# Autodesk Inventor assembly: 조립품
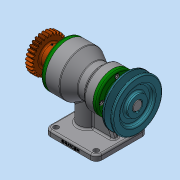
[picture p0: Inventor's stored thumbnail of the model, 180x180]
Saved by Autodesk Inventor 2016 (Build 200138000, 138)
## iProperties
Created: 2019-01
Part Number: 조립품
Material: 일반
Document SubType Name: Assembly
Designer: Administrator
Author: Administrator
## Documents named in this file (15)
- C:\Users\Administrator\Desktop\490108V1005\조립품.iam
- C:\Users\Administrator\Desktop\490108V1005\본체.ipt
- C:\Users\Administrator\Desktop\490108V1005\축.ipt
- C:\Users\Administrator\Desktop\490108V1005\베어링 6203.ipt
- C:\Users\Administrator\Desktop\490108V1005\베어링 6205.ipt
- C:\Users\Administrator\Desktop\490108V1005\뒤커버.ipt
- C:\Users\Administrator\Desktop\490108V1005\앞커버.ipt
- C:\Users\Administrator\Desktop\490108V1005\볼트 M4.ipt
- C:\Users\Administrator\Desktop\490108V1005\오일 실 17 30 8.ipt
- C:\Users\Administrator\Desktop\490108V1005\오일 실 25 38 8.ipt
- C:\Users\Administrator\Desktop\490108V1005\키 5 x 5 x 20.ipt
- C:\Users\Administrator\Desktop\490108V1005\키 6 x 6 x 18.ipt
- C:\Users\Administrator\Desktop\490108V1005\V-벨트풀리.ipt
- C:\Users\Administrator\Desktop\490108V1005\스퍼기어.ipt
- C:\Users\Administrator\Desktop\490108V1005\멈춤나사 M3.ipt
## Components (1 placed, 1 different names)
1. V-벨트풀리:1
